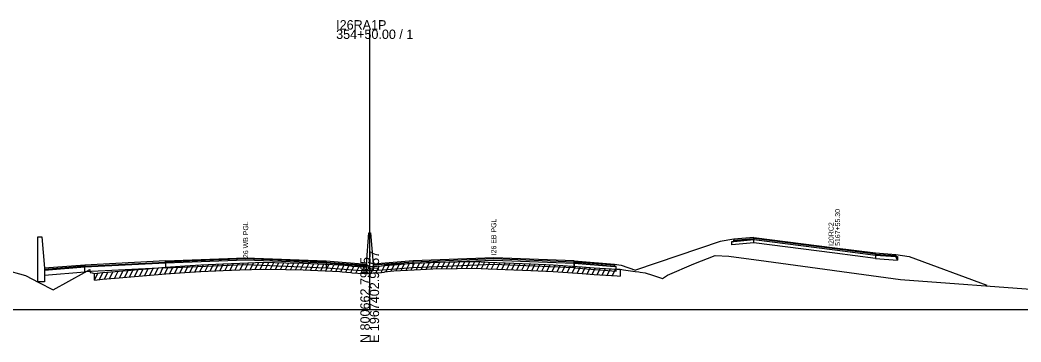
# Model space of a CAD drawing. Extents: x 1017 to 19997, y -1947 to 50737.
# Drawn here: x 14495.7 to 14794.3, y 4490.3 to 4586.3 of the extents above; entities that cross this region are included whole.
import ezdxf

# ---------------------------------------------------------------- set-up
doc = ezdxf.new("R2010")
doc.units = 0
for name, color, linetype in [('RD_GPK_XS_Cell', 7, 'Continuous'), ('RD_XS_Base', 7, 'Continuous'), ('RD_XS_ExGround', 7, 'Continuous'), ('RD_XS_ExPaveRet', 7, 'Continuous'), ('RD_XS_Greenside', 7, 'Continuous'), ('RD_XS_MedBWall', 7, 'Continuous'), ('RD_XS_Pave', 7, 'Continuous'), ('RD_XS_PaveOvlay', 7, 'Continuous'), ('RD_XS_TX_Notes', 7, 'Continuous')]:
    doc.layers.add(name, color=color, linetype=linetype)

msp = doc.modelspace()

# ---------------------------------------------------------------- linework, layer by layer
at = {"layer": 'RD_GPK_XS_Cell'}
for p, q in [((14600, 4500), (14600, 4583.45)), ((14000, 4500), (14600, 4500)), ((14600, 4500), (15200, 4500))]:
    msp.add_line(p, q, dxfattribs=at)
at = {"layer": 'RD_XS_Base'}
for points in [[(14708.06, 4520.26), (14708.57, 4520.31), (14714.61, 4520.83)], [(14708.06, 4519.26), (14708.06, 4520.26)], [(14714.61, 4519.83), (14714.61, 4520.83)], [(14714.61, 4519.83), (14708.06, 4519.26)], [(14750.87, 4515.21), (14738.78, 4516.75), (14714.61, 4519.83)], [(14750.87, 4516.21), (14750.87, 4515.21)], [(14757.41, 4514.74), (14756.91, 4515.78), (14750.87, 4516.21)], [(14750.87, 4516.21), (14756.91, 4515.78), (14757.41, 4515.74)], [(14750.87, 4515.21), (14757.41, 4514.74)], [(14757.41, 4515.74), (14757.41, 4514.74)], [(14515, 4512.57), (14503, 4511.61)], [(14503, 4511.61), (14503, 4510.27)], [(14503, 4510.27), (14515, 4511.23)], [(14515, 4511.23), (14515, 4512.57)], [(14539.05, 4512.43), (14515, 4511.23)], [(14539.05, 4513.77), (14539.05, 4512.43)], [(14539.05, 4512.43), (14563, 4513.4), (14587, 4512.44)], [(14599, 4512.84), (14587, 4513.78)], [(14587, 4513.78), (14587, 4512.44)], [(14587, 4512.44), (14599, 4511.5)], [(14599, 4511.5), (14599, 4512.84)], [(14601, 4511.5), (14601, 4512.84)], [(14613, 4512.44), (14601, 4511.5)], [(14613, 4512.44), (14613, 4513.78)], [(14660.95, 4512.44), (14637, 4513.4), (14613, 4512.44)], [(14660.95, 4512.44), (14660.95, 4513.78)], [(14661, 4512.44), (14660.95, 4512.44)], [(14661, 4513.78), (14661, 4512.44)], [(14673.5, 4512.78), (14673, 4512.82), (14661, 4513.78)], [(14661, 4512.44), (14673.5, 4511.44)], [(14673.5, 4511.44), (14673.5, 4512.78)]]:
    msp.add_lwpolyline(points, dxfattribs=at)
at = {"layer": 'RD_XS_ExGround'}
msp.add_lwpolyline([(14490.86, 4511.9), (14497.37, 4510.11), (14501.36, 4508), (14505.57, 4505.89), (14514.98, 4511.06), (14516.56, 4511.88), (14516.66, 4510.98), (14517.23, 4510.9), (14517.88, 4510.77), (14520.28, 4510.99), (14524.12, 4511.3), (14539.19, 4512.62), (14544.82, 4513.05), (14549.64, 4513.3), (14556.32, 4513.65), (14561.22, 4513.82), (14568.35, 4514.06), (14575.02, 4513.88), (14580.11, 4513.78), (14591.06, 4513.29), (14591.79, 4513.26), (14594.42, 4513.05), (14594.73, 4512.88), (14596.43, 4512.8), (14598.35, 4512.74), (14599.39, 4512.75), (14600, 4512.8), (14601.06, 4512.88), (14603.48, 4513.04), (14604.31, 4513.1), (14604.51, 4513.26), (14605.31, 4513.33), (14607.21, 4513.51), (14613.27, 4513.82), (14618.79, 4514.1), (14626.05, 4514.21), (14631.21, 4514.29), (14635.29, 4514.14), (14642.97, 4513.84), (14648.03, 4513.6), (14654.74, 4513.29), (14663.34, 4512.7), (14667, 4512.44), (14673.79, 4512.03), (14674.7, 4511.97), (14675.69, 4511.85), (14679.22, 4511.32), (14680.29, 4511.17), (14680.72, 4511.08), (14682.18, 4510.94), (14684.36, 4510.25), (14687.35, 4509.23), (14688.85, 4510.21), (14696.64, 4513.62), (14703, 4516.1), (14707.14, 4515.89), (14718.25, 4514.42), (14758.31, 4508.93), (14801.15, 4505.8)], dxfattribs=at)
at = {"layer": 'RD_XS_ExPaveRet'}
for p, q in [((14624.38, 4512.19), (14625.39, 4514.2)), ((14625.88, 4512.21), (14626.89, 4514.22)), ((14627.38, 4512.23), (14628.39, 4514.25)), ((14628.88, 4512.25), (14629.89, 4514.27)), ((14630.38, 4512.28), (14631.39, 4514.28)), ((14631.88, 4512.26), (14632.87, 4514.23)), ((14522.38, 4509.16), (14523.43, 4511.25)), ((14523.88, 4509.28), (14524.93, 4511.37)), ((14525.38, 4509.41), (14526.43, 4511.51)), ((14526.88, 4509.55), (14527.93, 4511.64)), ((14528.38, 4509.68), (14529.43, 4511.77)), ((14529.88, 4509.81), (14530.93, 4511.9)), ((14531.38, 4509.94), (14532.43, 4512.03)), ((14532.88, 4510.07), (14533.93, 4512.16)), ((14534.38, 4510.2), (14535.43, 4512.29)), ((14535.88, 4510.33), (14536.93, 4512.42)), ((14537.38, 4510.46), (14538.43, 4512.56)), ((14538.88, 4510.6), (14539.93, 4512.68)), ((14540.38, 4510.71), (14541.42, 4512.79)), ((14541.88, 4510.83), (14542.92, 4512.9)), ((14543.38, 4510.94), (14544.42, 4513.02)), ((14544.82, 4511.05), (14549.64, 4511.3)), ((14544.88, 4511.05), (14545.91, 4513.1)), ((14546.38, 4511.13), (14547.41, 4513.18)), ((14547.88, 4511.21), (14548.91, 4513.26)), ((14549.38, 4511.29), (14550.41, 4513.34)), ((14549.64, 4511.3), (14556.32, 4511.65)), ((14550.88, 4511.37), (14551.91, 4513.42)), ((14552.38, 4511.44), (14553.41, 4513.5)), ((14553.88, 4511.52), (14554.91, 4513.58)), ((14555.38, 4511.6), (14556.41, 4513.66)), ((14556.32, 4511.65), (14561.22, 4511.82)), ((14556.88, 4511.67), (14557.9, 4513.71)), ((14558.38, 4511.72), (14559.4, 4513.76)), ((14559.88, 4511.78), (14560.9, 4513.81)), ((14561.22, 4511.82), (14568.35, 4512.06)), ((14561.38, 4511.83), (14562.4, 4513.86)), ((14562.88, 4511.88), (14563.9, 4513.91)), ((14564.38, 4511.93), (14565.4, 4513.96)), ((14565.88, 4511.98), (14566.9, 4514.01)), ((14567.38, 4512.03), (14568.4, 4514.06)), ((14568.35, 4512.06), (14575.02, 4511.88)), ((14568.88, 4512.05), (14569.87, 4514.02)), ((14570.38, 4512.01), (14571.37, 4513.98)), ((14571.88, 4511.97), (14572.87, 4513.94)), ((14573.38, 4511.93), (14574.37, 4513.9)), ((14574.88, 4511.89), (14575.87, 4513.87)), ((14575.02, 4511.88), (14580.11, 4511.78)), ((14576.38, 4511.86), (14577.38, 4513.84)), ((14577.88, 4511.83), (14578.88, 4513.81)), ((14579.38, 4511.8), (14580.37, 4513.77)), ((14580.11, 4511.78), (14591.06, 4511.29)), ((14580.88, 4511.75), (14581.86, 4513.7)), ((14582.38, 4511.68), (14583.36, 4513.64)), ((14583.88, 4511.61), (14584.86, 4513.57)), ((14585.38, 4511.55), (14586.36, 4513.5)), ((14586.88, 4511.48), (14587.86, 4513.44)), ((14588.38, 4511.41), (14589.36, 4513.37)), ((14589.88, 4511.35), (14590.86, 4513.3)), ((14591.06, 4511.29), (14591.79, 4511.26)), ((14591.38, 4511.28), (14592.35, 4513.21)), ((14591.79, 4511.26), (14594.42, 4511.05)), ((14592.88, 4511.17), (14593.85, 4513.09)), ((14594.38, 4511.05), (14595.29, 4512.85)), ((14595.88, 4510.82), (14596.87, 4512.78)), ((14597.38, 4510.77), (14598.37, 4512.74)), ((14598.88, 4510.75), (14599.91, 4512.79)), ((14600.38, 4510.83), (14601.42, 4512.9)), ((14601.88, 4510.93), (14602.92, 4513)), ((14603.38, 4511.03), (14604.5, 4513.25)), ((14604.31, 4511.1), (14604.51, 4511.26)), ((14604.51, 4511.26), (14605.31, 4511.33)), ((14604.88, 4511.29), (14605.93, 4513.39)), ((14605.31, 4511.33), (14607.21, 4511.51)), ((14606.38, 4511.43), (14607.43, 4513.53)), ((14607.21, 4511.51), (14613.27, 4511.82)), ((14607.88, 4511.55), (14608.91, 4513.6)), ((14609.38, 4511.62), (14610.41, 4513.68)), ((14610.88, 4511.7), (14611.91, 4513.75)), ((14612.38, 4511.77), (14613.41, 4513.83)), ((14613.27, 4511.82), (14618.79, 4512.1)), ((14613.88, 4511.85), (14614.91, 4513.9)), ((14615.38, 4511.93), (14616.41, 4513.98)), ((14616.88, 4512.01), (14617.91, 4514.06)), ((14618.38, 4512.08), (14619.4, 4514.11)), ((14618.79, 4512.1), (14626.05, 4512.21)), ((14619.88, 4512.12), (14620.89, 4514.14)), ((14621.38, 4512.14), (14622.39, 4514.16)), ((14622.88, 4512.16), (14623.89, 4514.18)), ((14626.05, 4512.21), (14631.21, 4512.29)), ((14631.21, 4512.29), (14635.29, 4512.14)), ((14633.38, 4512.21), (14634.37, 4514.17)), ((14634.88, 4512.15), (14635.87, 4514.11)), ((14635.29, 4512.14), (14642.97, 4511.84)), ((14636.38, 4512.09), (14637.37, 4514.06)), ((14637.88, 4512.04), (14638.87, 4514)), ((14639.38, 4511.98), (14640.37, 4513.94)), ((14640.88, 4511.92), (14641.87, 4513.88)), ((14642.38, 4511.87), (14643.36, 4513.82)), ((14642.97, 4511.84), (14648.03, 4511.6)), ((14643.88, 4511.8), (14644.86, 4513.75)), ((14645.38, 4511.73), (14646.36, 4513.68)), ((14646.88, 4511.65), (14647.86, 4513.61)), ((14648.03, 4511.6), (14654.74, 4511.29)), ((14648.38, 4511.58), (14649.36, 4513.54)), ((14649.88, 4511.51), (14650.86, 4513.47)), ((14651.38, 4511.44), (14652.36, 4513.4)), ((14652.88, 4511.38), (14653.86, 4513.33)), ((14654.38, 4511.31), (14655.36, 4513.25)), ((14654.74, 4511.29), (14663.34, 4510.7)), ((14655.88, 4511.21), (14656.85, 4513.15)), ((14657.38, 4511.11), (14658.35, 4513.04)), ((14658.88, 4511.01), (14659.85, 4512.94)), ((14660.38, 4510.9), (14661.35, 4512.84)), ((14661.88, 4510.8), (14662.85, 4512.73)), ((14663.38, 4510.7), (14664.35, 4512.63)), ((14664.88, 4510.59), (14665.85, 4512.52)), ((14666.38, 4510.48), (14667.35, 4512.42)), ((14667.88, 4510.39), (14668.86, 4512.33)), ((14669.38, 4510.3), (14670.36, 4512.24)), ((14670.88, 4510.21), (14671.86, 4512.15)), ((14672.38, 4510.12), (14673.36, 4512.06)), ((14674.7, 4511.97), (14674.7, 4509.97)), ((14517.88, 4508.77), (14518.93, 4510.87)), ((14517.88, 4508.77), (14517.88, 4510.77)), ((14517.88, 4508.77), (14520.28, 4508.99)), ((14519.38, 4508.91), (14520.43, 4511)), ((14520.28, 4508.99), (14524.12, 4509.3)), ((14520.88, 4509.04), (14521.93, 4511.12)), ((14524.12, 4509.3), (14539.19, 4510.62)), ((14539.19, 4510.62), (14544.82, 4511.05)), ((14594.42, 4511.05), (14594.73, 4510.88)), ((14594.73, 4510.88), (14596.43, 4510.8)), ((14596.43, 4510.8), (14598.35, 4510.74)), ((14598.35, 4510.74), (14599.39, 4510.75)), ((14599.39, 4510.75), (14600, 4510.8)), ((14600, 4510.8), (14601.06, 4510.88)), ((14601.06, 4510.88), (14603.48, 4511.04)), ((14603.48, 4511.04), (14604.31, 4511.1)), ((14663.34, 4510.7), (14667, 4510.44)), ((14667, 4510.44), (14673.79, 4510.03)), ((14673.79, 4510.03), (14674.7, 4509.97))]:
    msp.add_line(p, q, dxfattribs=at)
at = {"layer": 'RD_XS_Greenside'}
for points in [[(14704.54, 4520.27), (14679.27, 4511.73)], [(14708.57, 4520.94), (14704.54, 4520.27)], [(14756.91, 4516.41), (14760.94, 4515.81)], [(14760.94, 4515.81), (14784.12, 4507.28)], [(14673, 4513.49), (14675, 4513.16)], [(14675, 4513.16), (14679.27, 4511.73)]]:
    msp.add_lwpolyline(points, dxfattribs=at)
at = {"layer": 'RD_XS_MedBWall'}
for points in [[(14501, 4508.19), (14501, 4521.63)], [(14501, 4521.63), (14502.25, 4521.63), (14503, 4512.29)], [(14599, 4513.49), (14599.75, 4522.83)], [(14599.75, 4522.83), (14600.25, 4522.83), (14601, 4513.49)], [(14503, 4512.29), (14503, 4508.19)], [(14599, 4511.49), (14599, 4512.84), (14599, 4513.49)], [(14601, 4511.49), (14599, 4511.49)], [(14601, 4513.49), (14601, 4512.84), (14601, 4511.49)], [(14503, 4508.19), (14501, 4508.19)]]:
    msp.add_lwpolyline(points, dxfattribs=at)
at = {"layer": 'RD_XS_Pave'}
for points in [[(14708.57, 4520.63), (14714.61, 4521.15)], [(14714.61, 4520.83), (14708.57, 4520.31)], [(14708.57, 4520.31), (14708.57, 4520.63)], [(14750.87, 4516.53), (14738.78, 4518.07), (14714.61, 4521.15)], [(14714.61, 4521.15), (14714.61, 4520.83)], [(14714.61, 4520.83), (14738.78, 4517.75), (14750.87, 4516.21)], [(14587, 4513.78), (14563, 4514.74), (14539.05, 4513.77)], [(14660.95, 4514.12), (14637, 4515.08), (14613, 4514.12)], [(14613, 4513.78), (14637, 4514.74), (14660.95, 4513.78)], [(14750.87, 4516.21), (14750.87, 4516.53)], [(14750.87, 4516.53), (14756.91, 4516.1)], [(14756.91, 4515.78), (14750.87, 4516.21)], [(14756.91, 4516.1), (14756.91, 4515.78)], [(14515, 4512.91), (14503, 4511.95)], [(14503, 4511.95), (14503, 4511.61)], [(14515, 4512.91), (14539.05, 4514.11)], [(14539.05, 4513.77), (14515, 4512.57)], [(14515, 4512.57), (14515, 4512.91)], [(14539.05, 4514.11), (14539.05, 4513.77)], [(14587, 4514.12), (14587, 4513.78)], [(14587, 4514.12), (14599, 4513.18)], [(14599, 4513.18), (14599, 4512.84)], [(14613, 4514.12), (14601, 4513.18)], [(14601, 4512.84), (14613, 4513.78)], [(14601, 4513.18), (14601, 4512.84)], [(14613, 4513.78), (14613, 4514.12)], [(14660.95, 4514.12), (14661, 4514.12)], [(14660.95, 4513.78), (14660.95, 4514.12)], [(14661, 4513.78), (14660.95, 4513.78)], [(14661, 4514.12), (14661, 4513.78)], [(14661, 4513.78), (14673, 4512.82)], [(14673, 4512.82), (14673, 4513.16)]]:
    msp.add_lwpolyline(points, dxfattribs=at)
at = {"layer": 'RD_XS_PaveOvlay'}
for points in [[(14714.61, 4521.47), (14708.57, 4520.94)], [(14708.57, 4520.94), (14708.57, 4520.63)], [(14714.61, 4521.47), (14738.78, 4518.38), (14750.87, 4516.85)], [(14714.61, 4521.15), (14714.61, 4521.47)], [(14539.05, 4514.45), (14515, 4513.25)], [(14539.05, 4514.45), (14563, 4515.41), (14587, 4514.45)], [(14587, 4514.12), (14563, 4515.08), (14539.05, 4514.11)], [(14539.05, 4514.11), (14539.05, 4514.45)], [(14587, 4514.45), (14587, 4514.12)], [(14587, 4514.45), (14599, 4513.49)], [(14613, 4514.45), (14601, 4513.49)], [(14660.95, 4514.45), (14637, 4515.41), (14613, 4514.45)], [(14613, 4514.12), (14613, 4514.45)], [(14660.95, 4514.45), (14661, 4514.45)], [(14660.95, 4514.12), (14660.95, 4514.45)], [(14661, 4514.45), (14673, 4513.49)], [(14661, 4514.12), (14661, 4514.45)], [(14750.87, 4516.85), (14750.87, 4516.53)], [(14750.87, 4516.85), (14756.91, 4516.41)], [(14756.91, 4516.41), (14756.91, 4516.1)], [(14515, 4513.25), (14503, 4512.29)], [(14503, 4512.29), (14503, 4511.95)], [(14515, 4513.25), (14515, 4512.91)], [(14599, 4513.49), (14599, 4513.18)], [(14601, 4513.49), (14601, 4513.18)], [(14673, 4513.16), (14661, 4514.12)], [(14673, 4513.49), (14673, 4513.16)]]:
    msp.add_lwpolyline(points, dxfattribs=at)

# ---------------------------------------------------------------- texts
at = {"layer": 'RD_GPK_XS_Cell'}
for s, p in [('I26RA1P', (14590, 4583.45)), ('354+50.00 / 1', (14590, 4580.65))]:
    msp.add_text(s, height=2.8, dxfattribs=at).set_placement(p)
for s, p in [('E 1967402.9157', (14602.8, 4490)), ('N 800662.7965', (14600, 4490))]:
    msp.add_text(s, height=2.8, rotation=90, dxfattribs=at).set_placement(p)
at = {"layer": 'RD_XS_TX_Notes'}
for s, p in [(' 5167+55.30', (14740.31, 4518.38)), ('I26 EB PGL', (14637.75, 4516.14)), ('I26 WB PGL', (14563.75, 4514.77)), (' I20RC2', (14738.36, 4518.38))]:
    msp.add_text(s, height=1.5, rotation=90, dxfattribs=at).set_placement(p)

doc.saveas('drawing.dxf')
